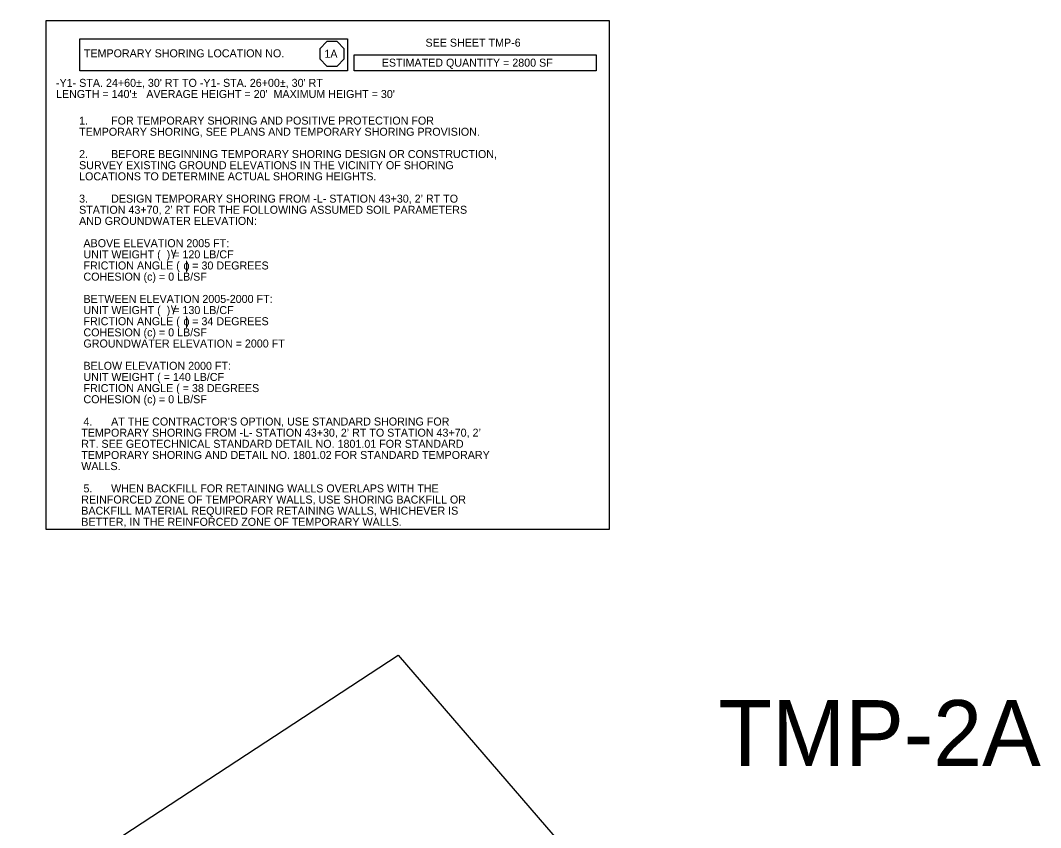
# Model space of a CAD drawing. Extents: x 2487012 to 2497594, y 369516 to 371986.
# Drawn here: x 2489515 to 2490384, y 371299 to 371986 of the extents above; entities that cross this region are included whole.
import ezdxf

# ---------------------------------------------------------------- set-up
doc = ezdxf.new("R2010")
doc.units = 0
for name, color, linetype in [('Scratch_Level_6', 7, 'Continuous'), ('TC LABEL TEMP SHORING', 7, 'Continuous'), ('TC SHEET BORDER LINE THIN', 7, 'Continuous'), ('TC SHEET LAYOUT SHAPE', 7, 'Continuous'), ('TC SHEET TEXT', 7, 'Continuous')]:
    doc.layers.add(name, color=color, linetype=linetype)

msp = doc.modelspace()

# ---------------------------------------------------------------- linework, layer by layer
at = {"layer": 'Scratch_Level_6'}
msp.add_lwpolyline([(2489016.56, 371282.27), (2489028.88, 371239.13), (2489430.44, 371433.43), (2489521.78, 371239.13), (2489836.55, 371445.42), (2490014.68, 371239.13), (2488843.26, 370955.22), (2489028.88, 370792.26), (2489389.17, 370953.89), (2489521.78, 370792.26), (2489877.82, 370924.58), (2490014.68, 370792.26)], dxfattribs=at)
at = {"layer": 'TC LABEL TEMP SHORING'}
for p, q in [((2489776, 371968.34), (2489769.91, 371962.17)), ((2489769.91, 371962.17), (2489769.91, 371953.45)), ((2489784.61, 371968.34), (2489776, 371968.34)), ((2489790.7, 371962.17), (2489784.61, 371968.34)), ((2489790.7, 371953.45), (2489790.7, 371962.17)), ((2489769.91, 371953.45), (2489776, 371947.28)), ((2489784.61, 371947.28), (2489790.7, 371953.45)), ((2489776, 371947.28), (2489784.61, 371947.28))]:
    msp.add_line(p, q, dxfattribs=at)
at = {"layer": 'TC SHEET BORDER LINE THIN'}
for points in [[(2489537.04, 371986.3), (2490016.48, 371986.3), (2490016.48, 371552.67), (2489537.04, 371552.67)], [(2489565.53, 371970.71), (2489793.58, 371970.71), (2489793.58, 371943.46), (2489565.53, 371943.46)], [(2489799.35, 371957.09), (2490005.13, 371957.09), (2490005.13, 371943.46), (2489799.35, 371943.46)]]:
    msp.add_lwpolyline(points, close=True, dxfattribs=at)

# ---------------------------------------------------------------- texts
at = {"layer": 'TC LABEL TEMP SHORING'}
for s, height, p in [('1A', 6.814, (2489773.89, 371954.45)), ('γ', 7.2, (2489643.09, 371785.51)), ('    ɸ', 7.2, (2489643.09, 371773.99)), ('γ', 7.2, (2489643.09, 371738.04)), ('    ɸ', 7.2, (2489643.09, 371726.52))]:
    msp.add_text(s, height=height, dxfattribs=at).set_placement(p)
at = {"layer": 'TC SHEET BORDER LINE THIN'}
for s, height, p in [('1.', 6.814, (2489565.03, 371897.52)), ('FOR TEMPORARY SHORING AND POSITIVE PROTECTION FOR ', 6.8137, (2489592.28, 371897.52)), ('TEMPORARY SHORING, SEE PLANS AND TEMPORARY SHORING PROVISION.', 6.8137, (2489565.03, 371888.03)), ('2.', 6.814, (2489565.03, 371869.04)), ('BEFORE BEGINNING TEMPORARY SHORING DESIGN OR CONSTRUCTION, ', 6.8137, (2489592.28, 371869.04)), ('SURVEY EXISTING GROUND ELEVATIONS IN THE VICINITY OF SHORING ', 6.8137, (2489565.03, 371859.55)), ('LOCATIONS TO DETERMINE ACTUAL SHORING HEIGHTS.', 6.8137, (2489565.03, 371850.05)), ('3.', 6.814, (2489565.03, 371831.06)), ('DESIGN TEMPORARY SHORING FROM -L- STATION 43+30, 2’ RT TO ', 6.8137, (2489592.28, 371831.06)), ('STATION 43+70, 2’ RT FOR THE FOLLOWING ASSUMED SOIL PARAMETERS ', 6.8137, (2489565.03, 371821.57)), ('AND GROUNDWATER ELEVATION:', 6.8137, (2489565.03, 371812.08)), ('ABOVE ELEVATION 2005 FT:', 6.8137, (2489568.74, 371793.09)), ('UNIT WEIGHT (  ) = 120 LB/CF', 6.8137, (2489568.74, 371783.59)), ('FRICTION ANGLE (  ) = 30 DEGREES', 6.8137, (2489568.74, 371774.1)), ('COHESION (c) = 0 LB/SF', 6.8137, (2489568.74, 371764.6)), ('BETWEEN ELEVATION 2005-2000 FT:', 6.8137, (2489568.74, 371745.61)), ('UNIT WEIGHT (  ) = 130 LB/CF', 6.8137, (2489568.74, 371736.12)), ('FRICTION ANGLE (  ) = 34 DEGREES', 6.8137, (2489568.74, 371726.63)), ('COHESION (c) = 0 LB/SF', 6.8137, (2489568.74, 371717.13)), ('GROUNDWATER ELEVATION = 2000 FT', 6.8137, (2489568.74, 371707.64)), ('BELOW ELEVATION 2000 FT:', 6.8137, (2489568.74, 371688.65)), ('UNIT WEIGHT ( = 140 LB/CF', 6.8137, (2489568.74, 371679.15)), ('FRICTION ANGLE ( = 38 DEGREES', 6.8137, (2489568.74, 371669.66)), ('COHESION (c) = 0 LB/SF', 6.8137, (2489568.74, 371660.17)), ('4.', 6.814, (2489568.74, 371641.18)), ('AT THE CONTRACTOR’S OPTION, USE STANDARD SHORING FOR ', 6.8137, (2489592.28, 371641.18)), ('TEMPORARY SHORING FROM -L- STATION 43+30, 2’ RT TO STATION 43+70, 2’ ', 6.8137, (2489566.88, 371631.68)), ('RT. SEE GEOTECHNICAL STANDARD DETAIL NO. 1801.01 FOR STANDARD ', 6.8137, (2489566.88, 371622.19)), ('TEMPORARY SHORING AND DETAIL NO. 1801.02 FOR STANDARD TEMPORARY ', 6.8137, (2489566.88, 371612.69)), ('WALLS.', 6.814, (2489566.88, 371603.2)), ('5.', 6.814, (2489568.74, 371584.21)), ('WHEN BACKFILL FOR RETAINING WALLS OVERLAPS WITH THE ', 6.8137, (2489592.28, 371584.21)), ('REINFORCED ZONE OF TEMPORARY WALLS, USE SHORING BACKFILL OR ', 6.8137, (2489566.88, 371574.72)), ('BACKFILL MATERIAL REQUIRED FOR RETAINING WALLS, WHICHEVER IS ', 6.8137, (2489566.88, 371565.22)), ('BETTER, IN THE REINFORCED ZONE OF TEMPORARY WALLS.', 6.8137, (2489566.88, 371555.73))]:
    msp.add_text(s, height=height, dxfattribs=at).set_placement(p)
at = {"layer": 'TC SHEET LAYOUT SHAPE'}
msp.add_text('TMP-2A', height=55.996, rotation=0.00008, dxfattribs=at).set_placement((2490109.23, 371351.23))
at = {"layer": 'TC SHEET TEXT'}
for s, p in [('SEE SHEET TMP-6', (2489859.97, 371963.92)), ('TEMPORARY SHORING LOCATION NO.', (2489569.1, 371954.85)), ('ESTIMATED QUANTITY = 2800 SF', (2489822.74, 371946.87)), ("-Y1- STA. 24+60±, 30' RT TO -Y1- STA. 26+00±, 30' RT", (2489545.38, 371929.68)), ("LENGTH = 140'±   AVERAGE HEIGHT = 20'  MAXIMUM HEIGHT = 30'", (2489545.38, 371920.19))]:
    msp.add_text(s, height=6.8137, dxfattribs=at).set_placement(p)

doc.saveas('drawing.dxf')
